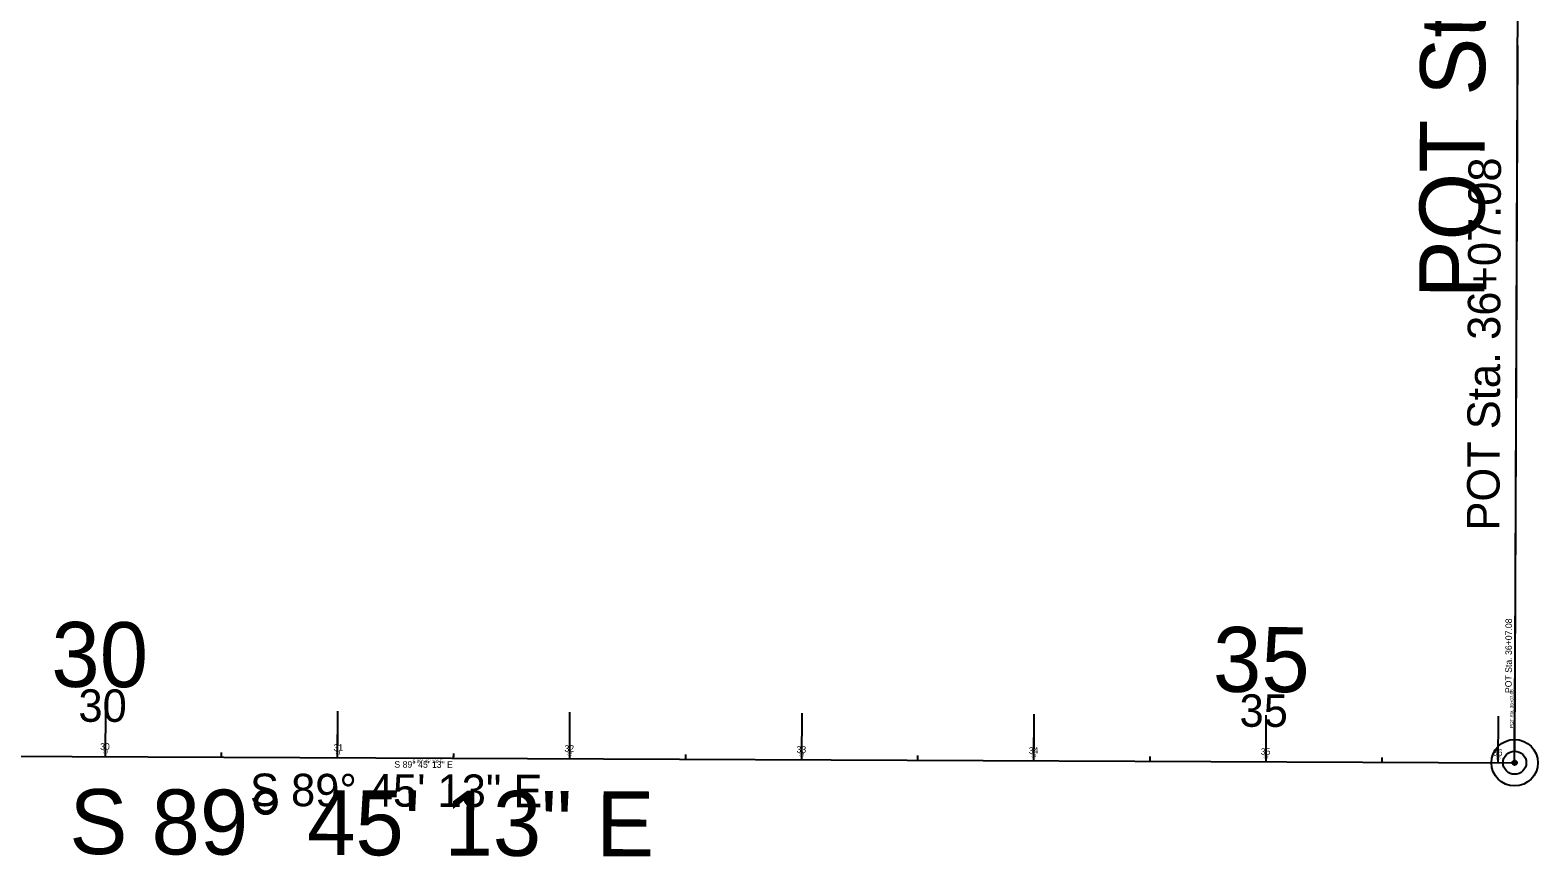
# Model space of a CAD drawing. Extents: x 1794716 to 1797874, y 325521 to 329174.
# Drawn here: x 1797225 to 1797874, y 327466 to 327822 of the extents above; entities that cross this region are included whole.
import ezdxf

# ---------------------------------------------------------------- set-up
doc = ezdxf.new("R2010")
doc.units = 0
for name, color, linetype in [('GE_P_CL_10', 7, 'Continuous'), ('GE_P_CL_100', 7, 'Continuous'), ('GE_P_CL_20', 7, 'Continuous'), ('GE_P_CL_200', 7, 'Continuous'), ('GE_P_CL_25', 7, 'Continuous'), ('GE_X_CL_30', 7, 'Continuous')]:
    doc.layers.add(name, color=color, linetype=linetype)

msp = doc.modelspace()

# ---------------------------------------------------------------- linework, layer by layer
at = {"layer": 'GE_P_CL_10'}
for p, q in [((1797864.11, 327507.24), (1797864.26, 327542.65)), ((1796930, 327510.75), (1797864.11, 327506.74)), ((1797257.03, 327509.35), (1797257.04, 327510.35)), ((1797307.03, 327509.13), (1797307.04, 327510.13)), ((1797357.03, 327508.92), (1797357.04, 327509.92)), ((1797407.03, 327508.7), (1797407.04, 327509.7)), ((1797457.03, 327508.49), (1797457.03, 327509.49)), ((1797507.03, 327508.27), (1797507.03, 327509.27)), ((1797557.03, 327508.06), (1797557.03, 327509.06)), ((1797607.03, 327507.84), (1797607.03, 327508.84)), ((1797657.03, 327507.63), (1797657.03, 327508.63)), ((1797707.03, 327507.41), (1797707.03, 327508.41)), ((1797757.03, 327507.2), (1797757.03, 327508.2)), ((1797807.03, 327506.98), (1797807.03, 327507.98)), ((1797857.03, 327506.77), (1797857.03, 327507.77))]:
    msp.add_line(p, q, dxfattribs=at)
msp.add_circle((1797864.11, 327506.74), 0.5, dxfattribs=at)
at = {"layer": 'GE_P_CL_100'}
for p, q in [((1797864.13, 327511.74), (1797865.43, 327815.88)), ((1797257.03, 327509.35), (1797257.08, 327519.35)), ((1797357.03, 327508.92), (1797357.07, 327518.92)), ((1797457.03, 327508.49), (1797457.07, 327518.49)), ((1797557.03, 327508.06), (1797557.07, 327518.06)), ((1797657.03, 327507.63), (1797657.07, 327517.63)), ((1797757.03, 327507.2), (1797757.07, 327517.2)), ((1797857.03, 327506.77), (1797857.07, 327516.77)), ((1796930, 327510.75), (1797864.11, 327506.74))]:
    msp.add_line(p, q, dxfattribs=at)
msp.add_circle((1797864.11, 327506.74), 5, dxfattribs=at)
at = {"layer": 'GE_P_CL_20'}
for p, q in [((1796930, 327510.75), (1797864.11, 327506.74)), ((1797257.03, 327509.35), (1797257.04, 327511.35)), ((1797307.03, 327509.13), (1797307.04, 327511.13)), ((1797357.03, 327508.92), (1797357.04, 327510.92)), ((1797407.03, 327508.7), (1797407.04, 327510.7)), ((1797457.03, 327508.49), (1797457.04, 327510.49)), ((1797507.03, 327508.27), (1797507.04, 327510.27)), ((1797557.03, 327508.06), (1797557.04, 327510.06)), ((1797607.03, 327507.84), (1797607.04, 327509.84)), ((1797657.03, 327507.63), (1797657.04, 327509.63)), ((1797707.03, 327507.41), (1797707.04, 327509.41)), ((1797757.03, 327507.2), (1797757.04, 327509.2)), ((1797807.03, 327506.98), (1797807.04, 327508.98)), ((1797857.03, 327506.77), (1797857.04, 327508.77))]:
    msp.add_line(p, q, dxfattribs=at)
at = {"layer": 'GE_P_CL_200'}
for p, q in [((1797864.15, 327516.74), (1797866.76, 328125.02)), ((1797257.03, 327509.35), (1797257.12, 327529.35)), ((1797357.03, 327508.92), (1797357.12, 327528.92)), ((1797457.03, 327508.49), (1797457.12, 327528.49)), ((1797557.03, 327508.06), (1797557.12, 327528.06)), ((1797657.03, 327507.63), (1797657.11, 327527.63)), ((1797757.03, 327507.2), (1797757.11, 327527.2)), ((1797857.03, 327506.77), (1797857.11, 327526.77)), ((1796930, 327510.75), (1797864.11, 327506.74))]:
    msp.add_line(p, q, dxfattribs=at)
msp.add_circle((1797864.11, 327506.74), 10, dxfattribs=at)
at = {"layer": 'GE_P_CL_25'}
msp.add_line((1797864.11, 327507.74), (1797864.41, 327578.57), dxfattribs=at)
msp.add_circle((1797864.11, 327506.74), 1, dxfattribs=at)
at = {"layer": 'GE_X_CL_30'}
msp.add_line((1796930, 327510.75), (1797864.11, 327506.74), dxfattribs=at)

# ---------------------------------------------------------------- texts
at = {"layer": 'GE_P_CL_10'}
for s, rotation, p in [('POT Sta. 36+07.08', 89.75374, (1797863.47, 327521.74)), ('30', 359.75374, (1797255.86, 327510.85)), ('31', 359.75374, (1797356.13, 327510.42)), ('32', 359.75374, (1797455.9, 327509.99)), ('33', 359.75374, (1797555.88, 327509.56)), ('34', 359.75374, (1797655.9, 327509.13)), ('35', 359.75374, (1797755.88, 327508.7)), ('36', 359.75374, (1797855.88, 327508.27)), ('S 89%%d 45\' 13" E', 359.75374, (1797389.27, 327506.68))]:
    msp.add_text(s, height=1.4, rotation=rotation, dxfattribs=at).set_placement(p)
at = {"layer": 'GE_P_CL_100'}
for s, rotation, p in [('POT Sta. 36+07.08', 89.75374, (1797857.54, 327606.77)), ('30', 359.75374, (1797245.36, 327524.4)), ('35', 359.75374, (1797745.57, 327522.25)), ('S 89%%d 45\' 13" E', 359.75374, (1797319.26, 327488.08))]:
    msp.add_text(s, height=14, rotation=rotation, dxfattribs=at).set_placement(p)
at = {"layer": 'GE_P_CL_20'}
for s, p in [('30', (1797254.7, 327512.36)), ('31', (1797355.23, 327511.93)), ('32', (1797454.76, 327511.5)), ('33', (1797554.73, 327511.07)), ('34', (1797654.77, 327510.64)), ('35', (1797754.74, 327510.21)), ('36', (1797854.72, 327509.78)), ('S 89%%d 45\' 13" E', (1797381.49, 327504.61))]:
    msp.add_text(s, height=2.8, rotation=359.75374, dxfattribs=at).set_placement(p)
at = {"layer": 'GE_P_CL_200'}
for s, rotation, p in [('POT Sta. 36+07.08', 89.75374, (1797850.97, 327706.8)), ('30', 359.75374, (1797233.68, 327539.45)), ('35', 359.75374, (1797734.12, 327537.3)), ('S 89%%d 45\' 13" E', 359.75374, (1797241.46, 327467.41))]:
    msp.add_text(s, height=28, rotation=rotation, dxfattribs=at).set_placement(p)
at = {"layer": 'GE_P_CL_25'}
msp.add_text('POT Sta. 36+07.08', height=2.8, rotation=89.75374, dxfattribs=at).set_placement((1797862.83, 327536.74))

doc.saveas('drawing.dxf')
